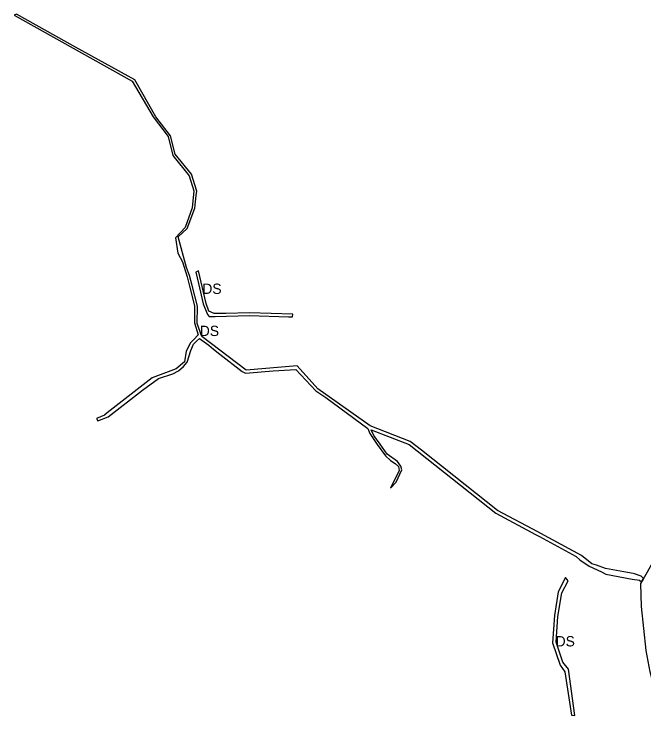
# Model space of a CAD drawing. Extents: x -477304 to -465641, y -1159113 to -1149285.
# Drawn here: x -473928 to -473380, y -1152630 to -1152011 of the extents above; entities that cross this region are included whole.
import ezdxf

# ---------------------------------------------------------------- set-up
doc = ezdxf.new("R2010")
doc.units = 0
doc.layers.add('35', color=7, linetype='Continuous')
doc.layers.add('4', color=7, linetype='Continuous')

msp = doc.modelspace()

# ---------------------------------------------------------------- linework, layer by layer
at = {"layer": '35'}
for p, q in [((-473925.74, -1152010.66), (-473927.85, -1152011.42)), ((-473927.85, -1152011.42), (-473825.17, -1152068.87)), ((-473804.64, -1152100.07), (-473823.03, -1152067.86)), ((-473791.98, -1152116.61), (-473804.64, -1152100.07)), ((-473793.91, -1152117.08), (-473789.76, -1152133.69)), ((-473789.76, -1152133.69), (-473775.51, -1152151.26)), ((-473769.38, -1152168.44), (-473768.94, -1152164.66)), ((-473770.7, -1152179.65), (-473769.38, -1152168.44)), ((-473777.22, -1152197.34), (-473770.7, -1152179.65)), ((-473785.11, -1152204.48), (-473777.22, -1152197.34)), ((-473760.88, -1152262.7), (-473767.5, -1152234.2)), ((-473776.82, -1152241.72), (-473775.3, -1152247.54)), ((-473775.3, -1152247.54), (-473770.82, -1152264.62)), ((-473770.82, -1152264.62), (-473771.05, -1152279.53)), ((-473758.51, -1152269.26), (-473760.88, -1152262.7)), ((-473753.72, -1152271.27), (-473758.51, -1152269.26)), ((-473743.71, -1152271.22), (-473753.72, -1152271.27)), ((-473758.12, -1152273.94), (-473752.91, -1152273.94)), ((-473752.91, -1152273.94), (-473723.21, -1152272.93)), ((-473723.21, -1152272.93), (-473689.15, -1152274.3)), ((-473771.05, -1152279.53), (-473767.88, -1152290.02)), ((-473764.54, -1152291.45), (-473768.72, -1152280.14)), ((-473774.35, -1152296.8), (-473778.25, -1152304.16)), ((-473771.73, -1152298.01), (-473769.08, -1152295.45)), ((-473769.08, -1152295.45), (-473766.61, -1152293.07)), ((-473766.61, -1152293.07), (-473758.58, -1152298.96)), ((-473725.86, -1152320.78), (-473764.54, -1152291.45)), ((-473758.58, -1152298.96), (-473754.34, -1152302.28)), ((-473754.34, -1152302.28), (-473748.88, -1152306.75)), ((-473816.28, -1152338.19), (-473802.41, -1152327.96)), ((-473656.68, -1152344.52), (-473620.03, -1152371.34)), ((-473847.06, -1152357.93), (-473849.24, -1152359.86)), ((-473849.24, -1152359.86), (-473856.16, -1152362.89)), ((-473856.16, -1152362.89), (-473854.98, -1152364.79)), ((-473507.34, -1152442.83), (-473573.48, -1152390.45)), ((-473600.37, -1152399.2), (-473596.33, -1152401.82)), ((-473596.33, -1152401.82), (-473593.51, -1152404.7)), ((-473592.92, -1152408.06), (-473600.46, -1152423.29)), ((-473595.36, -1152418.16), (-473590.36, -1152407.5)), ((-473593.51, -1152404.7), (-473592.92, -1152408.06)), ((-473600.46, -1152423.29), (-473595.36, -1152418.16)), ((-473508.81, -1152445.25), (-473474.14, -1152463.69)), ((-473434.06, -1152482), (-473469.41, -1152462.84)), ((-473438.75, -1152483.08), (-473435.61, -1152485.72)), ((-473425.1, -1152489.27), (-473434.06, -1152482)), ((-473420.99, -1152490.54), (-473425.1, -1152489.27)), ((-473413.32, -1152493.51), (-473420.99, -1152490.54)), ((-473397.4, -1152496.27), (-473413.32, -1152493.51)), ((-473445.63, -1152504.14), (-473448.18, -1152501.18)), ((-473416.76, -1152496.35), (-473413.08, -1152498.28)), ((-473413.08, -1152498.28), (-473390.07, -1152502.57)), ((-473389.02, -1152497.82), (-473397.4, -1152496.27)), ((-473387.87, -1152498.03), (-473389.02, -1152497.82)), ((-473382.09, -1152499.96), (-473387.87, -1152498.03)), ((-473380.1, -1152502), (-473382.09, -1152499.96)), ((-473451.17, -1152514.71), (-473445.63, -1152504.14)), ((-473390.07, -1152502.57), (-473383.57, -1152503.6)), ((-473383.57, -1152503.6), (-473381.97, -1152505.14)), ((-473454.7, -1152535.09), (-473451.17, -1152514.71)), ((-473456.15, -1152557.61), (-473454.7, -1152535.09)), ((-473450.42, -1152575.01), (-473456.15, -1152557.61)), ((-473445.49, -1152580.96), (-473450.42, -1152575.01)), ((-473452.54, -1152577.58), (-473448.54, -1152583.26)), ((-473448.54, -1152583.26), (-473442.75, -1152621.12))]:
    msp.add_line(p, q, dxfattribs=at)
for points in [[(-473823.03, -1152067.86), (-473874.47, -1152039.23), (-473925.74, -1152010.66)], [(-473825.17, -1152068.87), (-473807, -1152099.96), (-473793.91, -1152117.08)], [(-473768.94, -1152164.66), (-473773.64, -1152149.93), (-473787.8, -1152132.61), (-473791.98, -1152116.61)], [(-473775.51, -1152151.26), (-473771.42, -1152164.36), (-473773.09, -1152179.21)], [(-473773.09, -1152179.21), (-473778.97, -1152196.41), (-473787.57, -1152205.33), (-473785.39, -1152218.72)], [(-473775.28, -1152238.12), (-473777.89, -1152231.12), (-473785.11, -1152204.48)], [(-473785.39, -1152218.72), (-473781.41, -1152226.34), (-473777.4, -1152239.51), (-473776.82, -1152241.72)], [(-473767.5, -1152234.2), (-473769.68, -1152235.36), (-473767.45, -1152245.18), (-473763.47, -1152262.78)], [(-473768.72, -1152280.14), (-473768.24, -1152265), (-473772.99, -1152246.85), (-473775.28, -1152238.12)], [(-473763.47, -1152262.78), (-473759.63, -1152272.14), (-473758.12, -1152273.94)], [(-473685.48, -1152271.78), (-473723.04, -1152270.83), (-473743.71, -1152271.22)], [(-473689.15, -1152274.3), (-473685.79, -1152274.3), (-473685.48, -1152271.78)], [(-473767.88, -1152290.02), (-473771.85, -1152294.18), (-473774.35, -1152296.8)], [(-473802.41, -1152327.96), (-473789.92, -1152323.76), (-473784.99, -1152321.18), (-473780.56, -1152317.42), (-473777.25, -1152313.81), (-473774.06, -1152303.39), (-473771.73, -1152298.01)], [(-473778.25, -1152304.16), (-473779.78, -1152313.49), (-473786.93, -1152319.54)], [(-473748.88, -1152306.75), (-473729.36, -1152321.9), (-473726.54, -1152323.13), (-473702.44, -1152321.32), (-473682.64, -1152319.97), (-473665.33, -1152338.58), (-473656.68, -1152344.52)], [(-473786.93, -1152319.54), (-473807.93, -1152327.44), (-473847.06, -1152357.93)], [(-473663.49, -1152336.91), (-473681.47, -1152316.77), (-473725.86, -1152320.78)], [(-473854.98, -1152364.79), (-473846.13, -1152361.36), (-473816.28, -1152338.19)], [(-473573.48, -1152390.45), (-473583.37, -1152382.91), (-473617.98, -1152369.25), (-473663.49, -1152336.91)], [(-473620.03, -1152371.34), (-473618.32, -1152375.7), (-473611.96, -1152385.3), (-473604.61, -1152395.25), (-473600.37, -1152399.2)], [(-473609.49, -1152385), (-473614.79, -1152377.7), (-473617.09, -1152372.52)], [(-473617.09, -1152372.52), (-473584.16, -1152385.3), (-473508.81, -1152445.25)], [(-473590.36, -1152407.5), (-473591.24, -1152404.38), (-473594.36, -1152400.26), (-473603.31, -1152393.84), (-473609.49, -1152385)], [(-473469.41, -1152462.84), (-473472.23, -1152461.58), (-473507.34, -1152442.83)], [(-473474.14, -1152463.69), (-473470.62, -1152465.48), (-473438.75, -1152483.08)], [(-473435.61, -1152485.72), (-473427.41, -1152491.26), (-473416.76, -1152496.35)], [(-473448.18, -1152501.18), (-473454.47, -1152513.64), (-473457.6, -1152534.31), (-473459.37, -1152558.07), (-473452.54, -1152577.58)], [(-473381.97, -1152505.14), (-473380.51, -1152502.73), (-473380.1, -1152502)], [(-473442.75, -1152621.12), (-473439.82, -1152621.36), (-473445.49, -1152580.96)]]:
    msp.add_lwpolyline(points, dxfattribs=at)
at = {"layer": '4'}
msp.add_lwpolyline([(-473335.26, -1152435.47), (-473348.47, -1152446.42), (-473362.36, -1152462.48), (-473372.14, -1152487.86), (-473380.51, -1152502.73), (-473382.77, -1152506.47), (-473382.28, -1152526.57), (-473378.1, -1152564.87), (-473374.65, -1152583.27), (-473362.74, -1152630.36)], dxfattribs=at)

# ---------------------------------------------------------------- texts
at = {"layer": '35'}
for p in [(-473764.12, -1152254.25), (-473766.31, -1152290.94), (-473456.6, -1152561.27)]:
    msp.add_text('DS', height=9, dxfattribs=at).set_placement(p)

doc.saveas('drawing.dxf')
